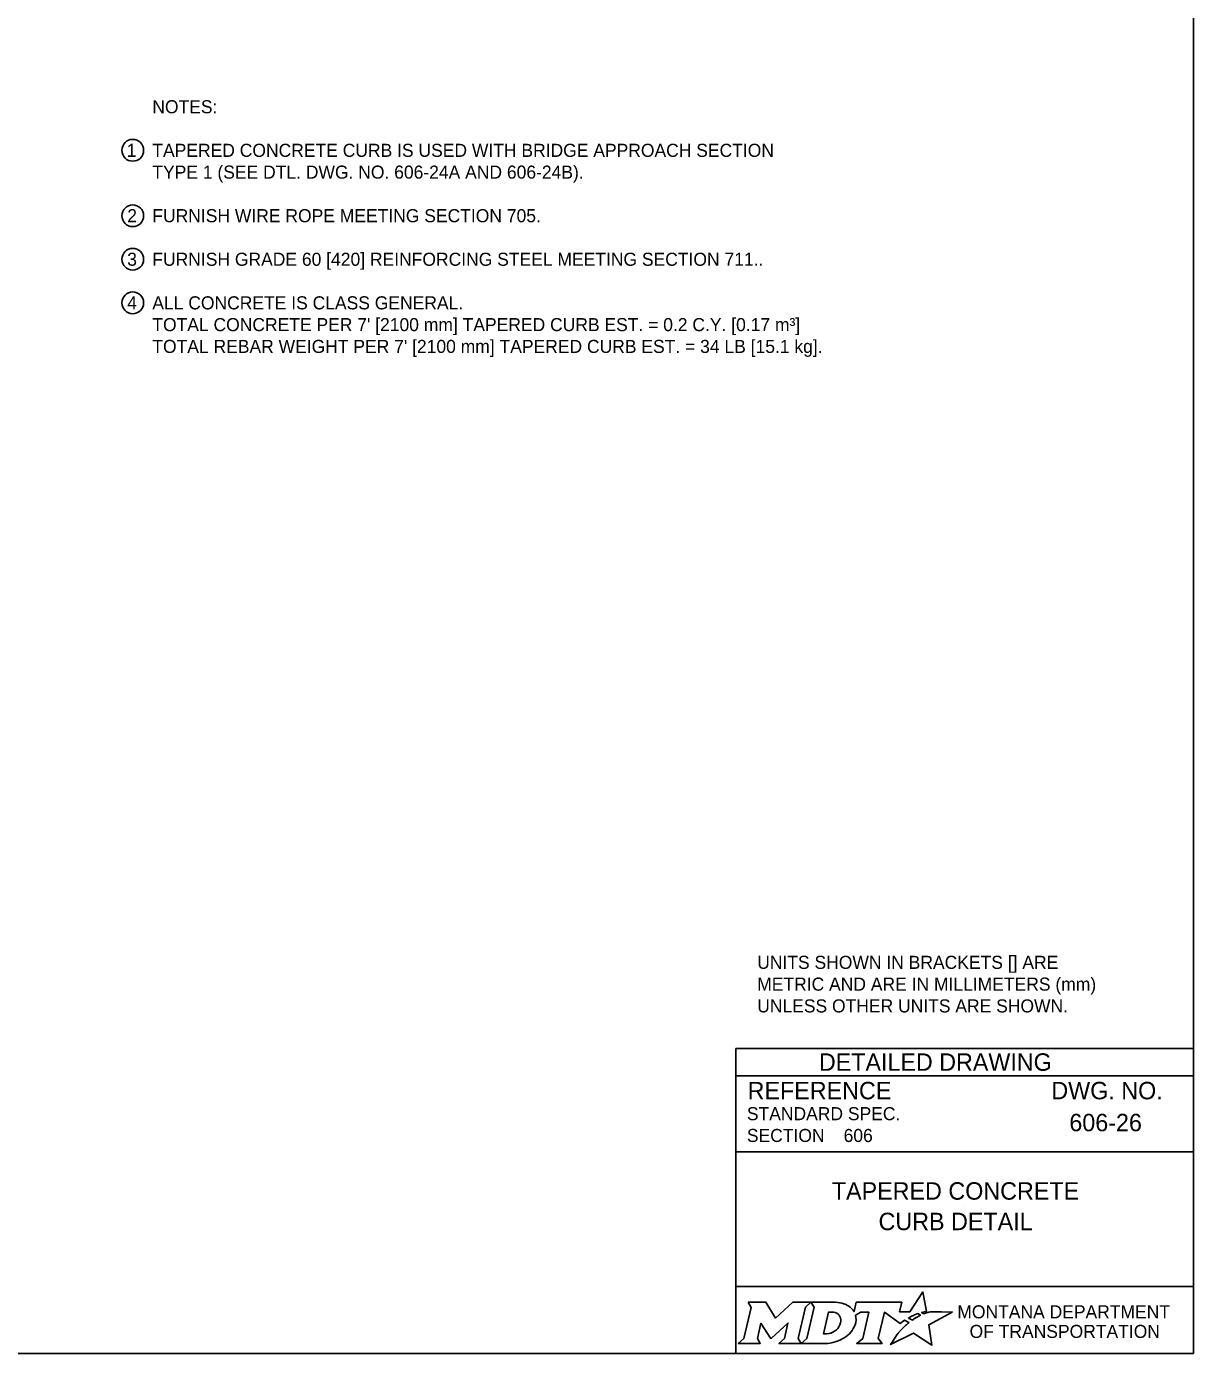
# Model space of a CAD drawing. Extents: x 49991.4 to 50021, y 49987.6 to 50011.4.
# Drawn here: x 50011.39 to 50016.75, y 49987.8 to 49993.89 of the extents above; entities that cross this region are included whole.
import ezdxf

# ---------------------------------------------------------------- set-up
doc = ezdxf.new("R2010")
doc.units = 0
for name, color, linetype in [('Default', 7, 'Continuous'), ('Level 1', 7, 'Continuous'), ('Level 2', 7, 'Continuous'), ('Level 5', 7, 'Continuous')]:
    doc.layers.add(name, color=color, linetype=linetype)

msp = doc.modelspace()

# ---------------------------------------------------------------- linework, layer by layer
at = {"layer": 'Default'}
for points in [[(50015.5126, 49987.9811), (50015.5023, 49987.9867), (50015.5139, 49987.9895), (50015.5255, 49987.9915), (50015.5081, 49988.0816), (50015.4486, 49987.9903), (50015.4013, 49987.9896), (50015.4116, 49988.0337), (50015.2024, 49988.0338), (50015.1923, 49987.9913), (50015.1865, 49987.9996)], [(50014.7056, 49988.0338), (50014.7197, 49988.0104), (50014.6862, 49987.8671), (50014.6605, 49987.8446), (50014.7621, 49987.8446), (50014.7486, 49987.8674), (50014.7648, 49987.9375), (50014.8085, 49987.8685), (50014.8138, 49987.8685), (50014.8889, 49987.938), (50014.8725, 49987.8669), (50014.8478, 49987.8449), (50014.9494, 49987.8449), (50014.9356, 49987.8682), (50014.9688, 49988.0106)], [(50014.9688, 49988.0106), (50014.9941, 49988.0338), (50014.9117, 49988.0338), (50014.8321, 49987.9608), (50014.7876, 49988.0335), (50014.7056, 49988.0338)], [(50015.1077, 49988.0338), (50014.9941, 49988.0338), (50015.0088, 49988.0109), (50014.9749, 49987.8671), (50014.9494, 49987.8449), (50015.06, 49987.8449)], [(50015.1317, 49987.9471), (50015.1305, 49987.939), (50015.1273, 49987.9297), (50015.1231, 49987.9215), (50015.1175, 49987.914), (50015.111, 49987.9071), (50015.1031, 49987.9008), (50015.0948, 49987.8961), (50015.0857, 49987.8922), (50015.0766, 49987.8899), (50015.0674, 49987.889), (50015.0515, 49987.889), (50015.0751, 49987.989), (50015.0911, 49987.989), (50015.0987, 49987.9884), (50015.1063, 49987.9865), (50015.1129, 49987.9835), (50015.119, 49987.9793), (50015.1238, 49987.9743), (50015.1275, 49987.9683), (50015.1302, 49987.9621), (50015.1318, 49987.9547), (50015.1318, 49987.9517), (50015.1317, 49987.9471)], [(50015.1991, 49987.9747), (50015.2237, 49987.9878), (50015.2606, 49987.9878), (50015.232, 49987.8673), (50015.2045, 49987.8446), (50015.3207, 49987.8446), (50015.3037, 49987.8675), (50015.3319, 49987.9877), (50015.4032, 49987.936), (50015.4243, 49987.9511), (50015.444, 49987.9402)], [(50015.3882, 49987.8843), (50015.3729, 49987.8599), (50015.3682, 49987.8524), (50015.3624, 49987.8438), (50015.3601, 49987.8395), (50015.4654, 49987.8926), (50015.5493, 49987.8375), (50015.5362, 49987.9302), (50015.6431, 49987.9886), (50015.5938, 49987.9894), (50015.5637, 49987.9898), (50015.5429, 49987.9901), (50015.5361, 49987.9886), (50015.5312, 49987.9874), (50015.5228, 49987.9851), (50015.5126, 49987.9811)], [(50015.4622, 49987.9535), (50015.4598, 49987.9518), (50015.4415, 49987.9614), (50015.4518, 49987.9671), (50015.4559, 49987.9693), (50015.4645, 49987.9733), (50015.4702, 49987.9759), (50015.4781, 49987.9789), (50015.4854, 49987.9816), (50015.4972, 49987.9742), (50015.4932, 49987.9721), (50015.4886, 49987.9696), (50015.4844, 49987.9674), (50015.4794, 49987.9645), (50015.4775, 49987.9634), (50015.4748, 49987.9618), (50015.4723, 49987.9604), (50015.47, 49987.9588), (50015.4674, 49987.957), (50015.4647, 49987.9552), (50015.4622, 49987.9535)], [(50015.1057, 49987.8522), (50015.1141, 49987.8548), (50015.1271, 49987.8602), (50015.1475, 49987.8712)], [(50015.4021, 49987.9004), (50015.4021, 49987.9004)]]:
    msp.add_lwpolyline(points, dxfattribs=at)
for centre, radius, start, end in [((50015.0868, 49987.9727), 0.1183, 300.91025, 339.13831), ((50015.1308, 49987.9554), 0.0709, 339.53292, 15.85821)]:
    msp.add_arc(centre, radius, start, end, dxfattribs=at)
for centre, major_axis, ratio, start_param, end_param in [((50015.1056, 49987.9864), (0.0834, -0.0037), 0.568097, 0.61298, 1.570796), ((50015.1612, 49987.9937), (0.0361, -0.0295), 0.469099, 1.225588, 1.570796), ((50015.4329, 49987.9305), (-0.0112, -0.0097), 0.021651, 3.157348, 6.283185), ((50015.3952, 49987.8923), (-0.00694, -0.00806), 0.008222, 0, 3.137361), ((50015.4119, 49987.9106), (-0.0098, -0.0102), 0.016458, 3.141593, 6.279097), ((50015.0603, 49987.9932), (0, 0.1484), 0.987302, 3.139398, 3.456847)]:
    msp.add_ellipse(centre, major_axis=major_axis, ratio=ratio, start_param=start_param, end_param=end_param, dxfattribs=at)
at = {"layer": 'Level 1'}
msp.add_lwpolyline([(49999.3835, 49998.9992), (50016.7501, 49998.9992), (50016.7501, 49987.7988), (49999.3835, 49987.7988)], close=True, dxfattribs=at)
at = {"layer": 'Level 2'}
for centre in [(50011.8816, 49993.321), (50011.8816, 49993.0209), (50011.8816, 49992.821), (50011.8816, 49992.621)]:
    msp.add_circle(centre, 0.05, dxfattribs=at)
at = {"layer": 'Level 5'}
for p, q in [((50016.7501, 49989.1988), (50014.6501, 49989.1988)), ((50014.6501, 49989.1988), (50014.6501, 49987.7988)), ((50016.7501, 49989.0738), (50014.6501, 49989.0738)), ((50016.3862, 49988.8587), (50016.3862, 49988.8587)), ((50015.1444, 49988.7993), (50015.1444, 49988.7993)), ((50016.7501, 49988.7238), (50014.6501, 49988.7238)), ((50015.7001, 49988.4747), (50015.7001, 49988.4747)), ((50016.7501, 49988.1057), (50014.6501, 49988.1057))]:
    msp.add_line(p, q, dxfattribs=at)

# ---------------------------------------------------------------- texts
at = {"layer": 'Default'}
for s, p in [('MONTANA DEPARTMENT', (50015.6663, 49987.96)), ('OF TRANSPORTATION', (50015.7225, 49987.87))]:
    msp.add_text(s, height=0.06, dxfattribs=at).set_placement(p)
at = {"layer": 'Level 2'}
for s, height, p in [('NOTES:', 0.06, (50011.9716, 49993.491)), ('1', 0.06, (50011.8538, 49993.2909)), ('TAPERED CONCRETE CURB IS USED WITH BRIDGE APPROACH SECTION', 0.06, (50011.9716, 49993.291)), ('TYPE 1 (SEE DTL. DWG. NO. 606-24A AND 606-24B).', 0.06, (50011.9716, 49993.191)), ('2', 0.06, (50011.8564, 49992.9909)), ('FURNISH WIRE ROPE MEETING SECTION 705.', 0.06, (50011.9716, 49992.991)), ('3', 0.06, (50011.8563, 49992.7911)), ('FURNISH GRADE 60 [420] REINFORCING STEEL MEETING SECTION 711..', 0.06, (50011.9716, 49992.791)), ('4', 0.06, (50011.8563, 49992.5912)), ('ALL CONCRETE IS CLASS GENERAL.', 0.06, (50011.9716, 49992.591)), ("TOTAL CONCRETE PER 7' [2100 mm] TAPERED CURB EST. = 0.2 C.Y. [0.17 m³]", 0.06, (50011.9716, 49992.491)), ("TOTAL REBAR WEIGHT PER 7' [2100 mm] TAPERED CURB EST. = 34 LB [15.1 kg].", 0.06, (50011.9716, 49992.391)), ('UNITS SHOWN IN BRACKETS [] ARE ', 0.06, (50014.7478, 49989.564)), ('METRIC AND ARE IN MILLIMETERS (mm) ', 0.06, (50014.7478, 49989.464)), ('UNLESS OTHER UNITS ARE SHOWN.', 0.06, (50014.7478, 49989.364)), ('606-26', 0.08, (50016.1804, 49988.8187)), ('606', 0.06, (50015.1444, 49988.7693)), ('TAPERED CONCRETE', 0.08, (50015.0902, 49988.5047)), ('CURB DETAIL', 0.08, (50015.3046, 49988.3647))]:
    msp.add_text(s, height=height, dxfattribs=at).set_placement(p)
at = {"layer": 'Level 5'}
for s, height, p in [('DETAILED DRAWING', 0.0799, (50015.0311, 49989.0963)), ('REFERENCE', 0.08, (50014.7037, 49988.9654)), ('DWG. NO.', 0.08, (50016.0979, 49988.9654)), ('STANDARD SPEC.', 0.06, (50014.7004, 49988.8694)), ('SECTION', 0.06, (50014.7004, 49988.7694))]:
    msp.add_text(s, height=height, dxfattribs=at).set_placement(p)

doc.saveas('drawing.dxf')
